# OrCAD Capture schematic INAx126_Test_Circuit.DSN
size A; title: INAx126 MicroPower Instrumentation Amplifier; rev: 1.1; note: Datasheet: SBOS062C  EVM: N/A
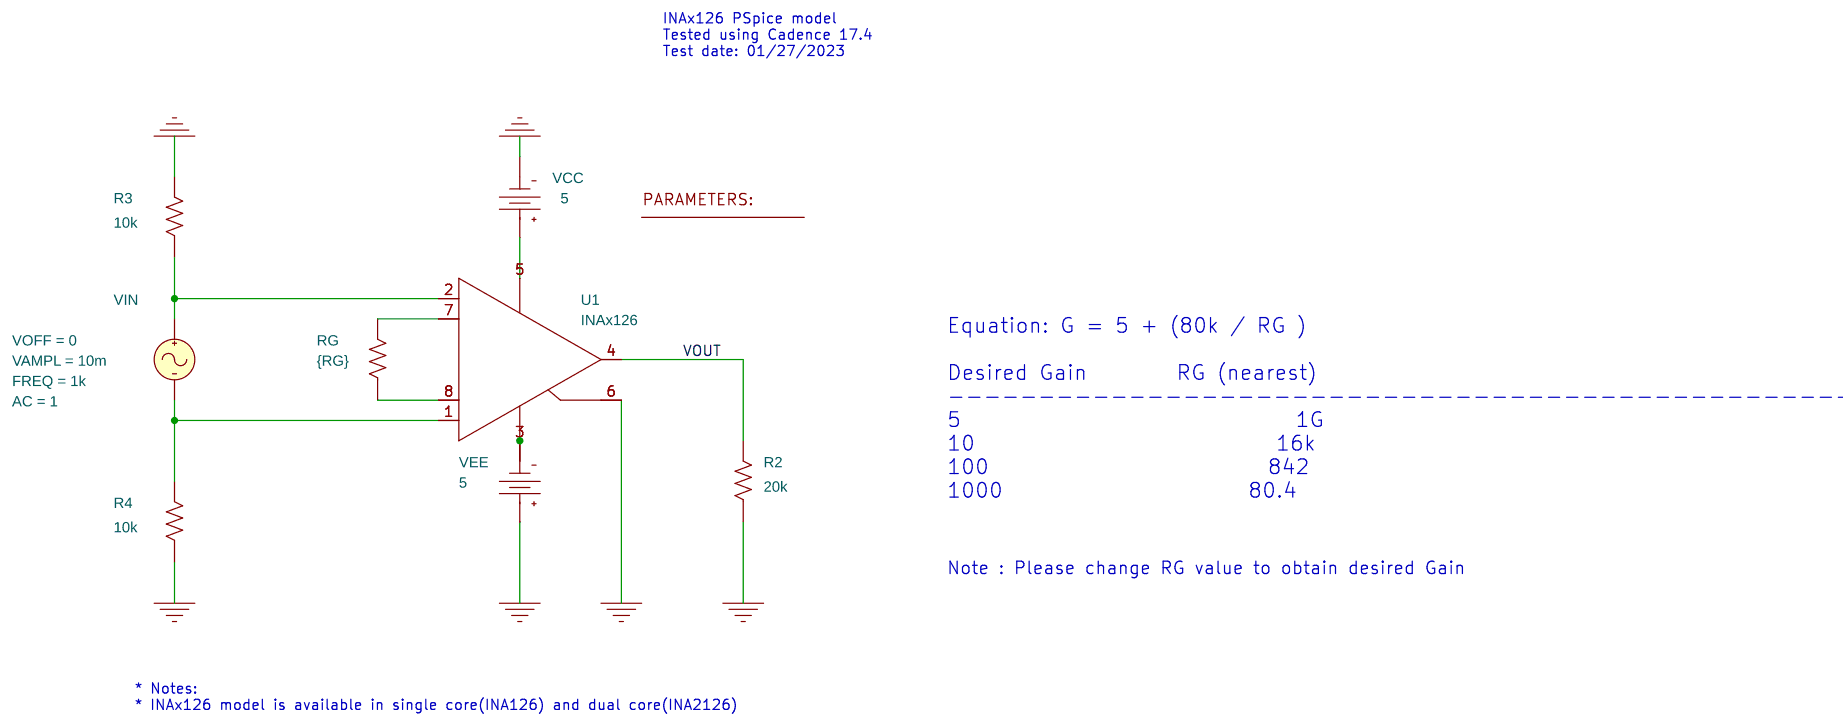
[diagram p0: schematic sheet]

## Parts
1  PARAM
R2  20k  [AX/RC05]
R3  10k  [AX/RC05]
R4  10k  [AX/RC05]
RG  {RG}  [AX/RC05]
U1  INAx126
VCC  VDC
VEE  VDC
VIN  VSIN

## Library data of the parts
1 = PARAM: RG: 842
R2-R4 RG = R
U1 = INAx126
VCC VEE = VDC: DC: 5
VIN = VSIN: AC: 1; FREQ: 1k; VAMPL: 10m; VOFF: 0

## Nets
0: R2.1 R3.2 R4.1 U1.6(REF) VCC.1(-) VEE.0(+)
VOUT: R2.2 U1.4(OUT)
N14300126: RG.2 U1.7(RG+)
N14300130: RG.1 U1.8(RG-)
N14300245: R4.2 U1.1(+) VIN.2(-)
N14300266: R3.1 U1.2(-) VIN.1(+)
N14300680: U1.5(V+) VCC.0(+)
N14300699: U1.3(V-) VEE.1(-)

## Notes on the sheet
- INAx126 PSpice model
  Tested using Cadence 17.4
  Test date: 01/27/2023
- Equation: G = 5 + (80k / RG )
  Desired Gain        RG (nearest)
  ----------------------------------------------------
  5                              1G
  10                           16k
  100                         842
  1000                      80.4
- Note : Please change RG value to obtain desired Gain
- * Notes:
  * INAx126 model is available in single core(INA126) and dual core(INA2126)
